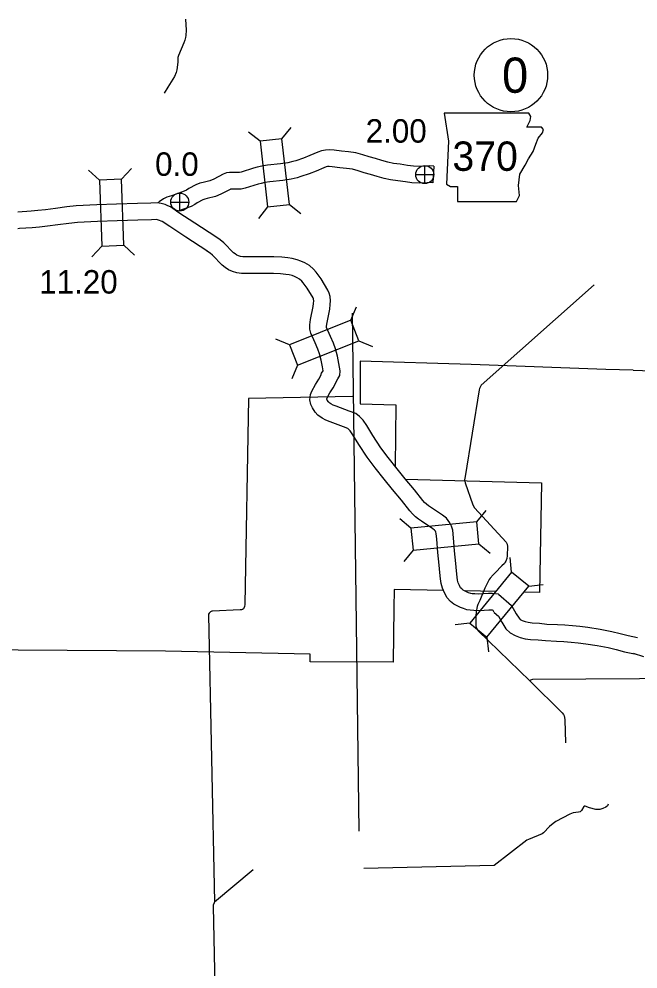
# Model space of a CAD drawing. Extents: x -939622 to -934245, y 1383184 to 1385301.
# Drawn here: x -936282.1 to -936248.7, y 1384082.8 to 1384134.1 of the extents above; entities that cross this region are included whole.
import ezdxf

# ---------------------------------------------------------------- set-up
doc = ezdxf.new("R2010")
doc.units = 0
for name, color, linetype in [('10', 7, 'Continuous'), ('20', 7, 'Continuous'), ('21', 7, 'Continuous'), ('25', 7, 'Continuous'), ('26', 7, 'Continuous'), ('27', 7, 'Continuous'), ('35', 7, 'Continuous'), ('8', 7, 'Continuous')]:
    doc.layers.add(name, color=color, linetype=linetype)

msp = doc.modelspace()

# ---------------------------------------------------------------- linework, layer by layer
at = {"layer": '10'}
for points in [[(-936259.691, 1384126.189), (-936259.9, 1384126.203), (-936260.112, 1384126.188), (-936260.441, 1384126.171), (-936260.797, 1384126.194), (-936261.113, 1384126.233), (-936261.51, 1384126.288), (-936261.874, 1384126.339), (-936262.17, 1384126.398), (-936262.501, 1384126.486), (-936262.845, 1384126.598), (-936263.188, 1384126.695), (-936263.52, 1384126.806), (-936263.899, 1384126.909), (-936264.302, 1384126.964), (-936264.673, 1384127), (-936265.074, 1384127.043), (-936265.325, 1384127.07), (-936265.545, 1384127.057), (-936265.753, 1384127.017), (-936265.962, 1384126.939), (-936266.383, 1384126.76), (-936266.733, 1384126.626), (-936267.14, 1384126.483), (-936267.306, 1384126.435), (-936267.569, 1384126.372), (-936267.967, 1384126.314), (-936268.676, 1384126.234), (-936268.981, 1384126.185), (-936269.221, 1384126.137), (-936269.428, 1384126.082), (-936270.099, 1384125.871), (-936270.185, 1384125.854), (-936270.339, 1384125.853), (-936270.727, 1384125.845), (-936270.888, 1384125.826), (-936271.073, 1384125.75), (-936271.57, 1384125.494), (-936271.78, 1384125.402), (-936272.142, 1384125.31), (-936272.323, 1384125.27), (-936272.539, 1384125.183), (-936272.917, 1384124.98), (-936273.049, 1384124.898), (-936273.165, 1384124.835), (-936273.456, 1384124.727), (-936273.856, 1384124.594), (-936274.097, 1384124.517), (-936274.277, 1384124.416), (-936274.518, 1384124.262), (-936274.577, 1384124.205)], [(-936259.748, 1384125.291), (-936259.898, 1384125.301), (-936260.057, 1384125.29), (-936260.446, 1384125.269), (-936260.881, 1384125.297), (-936261.229, 1384125.34), (-936261.634, 1384125.396), (-936262.025, 1384125.451), (-936262.375, 1384125.521), (-936262.756, 1384125.623), (-936263.107, 1384125.737), (-936263.454, 1384125.835), (-936263.781, 1384125.944), (-936264.078, 1384126.025), (-936264.405, 1384126.07), (-936264.764, 1384126.104), (-936265.172, 1384126.148), (-936265.346, 1384126.167), (-936265.431, 1384126.162), (-936265.51, 1384126.147), (-936265.629, 1384126.103), (-936266.045, 1384125.925), (-936266.424, 1384125.78), (-936266.866, 1384125.626), (-936267.076, 1384125.565), (-936267.399, 1384125.487), (-936267.851, 1384125.422), (-936268.553, 1384125.342), (-936268.823, 1384125.298), (-936269.019, 1384125.26), (-936269.177, 1384125.218), (-936269.875, 1384124.998), (-936270.094, 1384124.954), (-936270.328, 1384124.953), (-936270.66, 1384124.947), (-936270.695, 1384124.932), (-936271.184, 1384124.681), (-936271.487, 1384124.548), (-936271.933, 1384124.434), (-936272.057, 1384124.407), (-936272.157, 1384124.366), (-936272.466, 1384124.2), (-936272.596, 1384124.12), (-936272.792, 1384124.013), (-936273.158, 1384123.878), (-936273.572, 1384123.74)], [(-936259.691, 1384126.189), (-936259.748, 1384125.291)], [(-936271.46, 1384122.371), (-936272.589, 1384123.117), (-936273.452, 1384123.673), (-936273.91, 1384123.989), (-936274.054, 1384124.052), (-936274.204, 1384124.116), (-936274.42, 1384124.175), (-936274.625, 1384124.206), (-936274.968, 1384124.194), (-936275.697, 1384124.171), (-936276.815, 1384124.137), (-936277.877, 1384124.097), (-936278.997, 1384124.047), (-936279.497, 1384123.993), (-936280.117, 1384123.911), (-936280.654, 1384123.835), (-936281.061, 1384123.79), (-936281.438, 1384123.763), (-936282.149, 1384123.711)], [(-936271.955, 1384121.62), (-936273.081, 1384122.363), (-936273.951, 1384122.924), (-936274.35, 1384123.199), (-936274.41, 1384123.226), (-936274.5, 1384123.263), (-936274.607, 1384123.293), (-936274.677, 1384123.303), (-936274.939, 1384123.295), (-936275.669, 1384123.271), (-936276.784, 1384123.237), (-936277.84, 1384123.198), (-936278.928, 1384123.15), (-936279.39, 1384123.099), (-936279.996, 1384123.02), (-936280.542, 1384122.942), (-936280.978, 1384122.894), (-936281.373, 1384122.865), (-936282.062, 1384122.815), (-936282.141, 1384122.805)], [(-936256.198, 1384103.088), (-936256.545, 1384103.118), (-936256.735, 1384103.118), (-936257.017, 1384103.11), (-936257.259, 1384103.092), (-936257.488, 1384103.099), (-936257.631, 1384103.109), (-936257.697, 1384103.12), (-936257.819, 1384103.16), (-936257.897, 1384103.185), (-936257.995, 1384103.241), (-936258.102, 1384103.301), (-936258.186, 1384103.368), (-936258.247, 1384103.428), (-936258.316, 1384103.558), (-936258.378, 1384103.698), (-936258.413, 1384103.834), (-936258.434, 1384104), (-936258.468, 1384104.352), (-936258.511, 1384104.743), (-936258.578, 1384105.418), (-936258.634, 1384106.128), (-936258.673, 1384106.534), (-936258.741, 1384106.749), (-936258.828, 1384106.94), (-936259.006, 1384107.187), (-936259.227, 1384107.344), (-936259.866, 1384107.775), (-936259.988, 1384107.856), (-936260.093, 1384107.938), (-936260.19, 1384108.033), (-936260.286, 1384108.148), (-936260.744, 1384108.725), (-936261.234, 1384109.307), (-936261.672, 1384109.85), (-936262.158, 1384110.459), (-936262.559, 1384110.99), (-936262.985, 1384111.644), (-936263.308, 1384112.181), (-936263.514, 1384112.473), (-936263.708, 1384112.679), (-936263.907, 1384112.829), (-936264.264, 1384112.959), (-936264.958, 1384113.224), (-936265.129, 1384113.292), (-936265.256, 1384113.362), (-936265.359, 1384113.431), (-936265.384, 1384113.459), (-936265.452, 1384113.565), (-936265.469, 1384113.602), (-936265.474, 1384113.628), (-936265.474, 1384113.631), (-936265.464, 1384113.652), (-936265.307, 1384113.959), (-936265.133, 1384114.229), (-936264.983, 1384114.498), (-936264.948, 1384114.59), (-936264.873, 1384114.701), (-936264.767, 1384114.891), (-936264.745, 1384115.143), (-936264.815, 1384115.534), (-936264.898, 1384115.923), (-936265.009, 1384116.324), (-936265.117, 1384116.627), (-936265.265, 1384116.996), (-936265.481, 1384117.483), (-936265.489, 1384117.513), (-936265.489, 1384117.549), (-936265.458, 1384117.747), (-936265.313, 1384118.469), (-936265.281, 1384118.717), (-936265.278, 1384118.923), (-936265.287, 1384119.149), (-936265.339, 1384119.336), (-936265.416, 1384119.499), (-936265.778, 1384120.101), (-936266.038, 1384120.461), (-936266.189, 1384120.627), (-936266.412, 1384120.821), (-936266.662, 1384120.967), (-936266.87, 1384121.057), (-936267.062, 1384121.136), (-936267.34, 1384121.207), (-936267.568, 1384121.237), (-936267.901, 1384121.275), (-936268.333, 1384121.289), (-936269.106, 1384121.302), (-936269.816, 1384121.293), (-936270.01, 1384121.3), (-936270.136, 1384121.316), (-936270.241, 1384121.349), (-936270.335, 1384121.392), (-936270.422, 1384121.449), (-936270.499, 1384121.513), (-936271.035, 1384122.057), (-936271.235, 1384122.22), (-936271.456, 1384122.369)], [(-936256.436, 1384102.102), (-936256.488, 1384102.203), (-936256.519, 1384102.212), (-936256.583, 1384102.218), (-936256.722, 1384102.218), (-936256.972, 1384102.211), (-936257.239, 1384102.191), (-936257.531, 1384102.2), (-936257.735, 1384102.214), (-936257.914, 1384102.244), (-936258.098, 1384102.305), (-936258.26, 1384102.357), (-936258.437, 1384102.457), (-936258.606, 1384102.552), (-936258.786, 1384102.694), (-936258.978, 1384102.886), (-936259.125, 1384103.163), (-936259.231, 1384103.401), (-936259.3, 1384103.667), (-936259.328, 1384103.903), (-936259.363, 1384104.26), (-936259.406, 1384104.649), (-936259.475, 1384105.337), (-936259.531, 1384106.05), (-936259.56, 1384106.353), (-936259.583, 1384106.426), (-936259.61, 1384106.486), (-936259.649, 1384106.539), (-936259.74, 1384106.604), (-936260.367, 1384107.027), (-936260.514, 1384107.125), (-936260.685, 1384107.259), (-936260.852, 1384107.421), (-936260.985, 1384107.581), (-936261.44, 1384108.155), (-936261.929, 1384108.735), (-936262.374, 1384109.287), (-936262.868, 1384109.907), (-936263.296, 1384110.472), (-936263.748, 1384111.166), (-936264.063, 1384111.69), (-936264.212, 1384111.902), (-936264.312, 1384112.007), (-936264.342, 1384112.03), (-936264.577, 1384112.115), (-936265.286, 1384112.386), (-936265.515, 1384112.478), (-936265.725, 1384112.593), (-936265.951, 1384112.745), (-936266.1, 1384112.909), (-936266.249, 1384113.139), (-936266.329, 1384113.323), (-936266.384, 1384113.574), (-936266.355, 1384113.865), (-936266.276, 1384114.042), (-936266.088, 1384114.409), (-936265.905, 1384114.693), (-936265.8, 1384114.881), (-936265.752, 1384115.006), (-936265.659, 1384115.145), (-936265.698, 1384115.36), (-936265.772, 1384115.709), (-936265.867, 1384116.052), (-936265.959, 1384116.308), (-936266.094, 1384116.646), (-936266.33, 1384117.179), (-936266.389, 1384117.389), (-936266.39, 1384117.617), (-936266.344, 1384117.906), (-936266.202, 1384118.614), (-936266.181, 1384118.781), (-936266.179, 1384118.911), (-936266.183, 1384119.01), (-936266.186, 1384119.021), (-936266.211, 1384119.073), (-936266.529, 1384119.604), (-936266.738, 1384119.892), (-936266.821, 1384119.983), (-936266.94, 1384120.088), (-936267.068, 1384120.163), (-936267.22, 1384120.228), (-936267.345, 1384120.28), (-936267.51, 1384120.322), (-936267.677, 1384120.344), (-936267.966, 1384120.376), (-936268.355, 1384120.389), (-936269.108, 1384120.402), (-936269.827, 1384120.393), (-936270.083, 1384120.402), (-936270.328, 1384120.433), (-936270.564, 1384120.507), (-936270.77, 1384120.601), (-936270.958, 1384120.724), (-936271.11, 1384120.851), (-936271.642, 1384121.39), (-936271.772, 1384121.497), (-936271.959, 1384121.623)], [(-936256.198, 1384103.088), (-936255.498, 1384102.478), (-936255.243, 1384102.028), (-936255.094, 1384101.787), (-936255.024, 1384101.72), (-936254.927, 1384101.665), (-936254.768, 1384101.605), (-936254.6, 1384101.569), (-936254.379, 1384101.54), (-936253.99, 1384101.51), (-936253.594, 1384101.472), (-936253.019, 1384101.445), (-936252.624, 1384101.423), (-936252.208, 1384101.392), (-936251.809, 1384101.352), (-936251.371, 1384101.299), (-936250.718, 1384101.201), (-936250.091, 1384101.076), (-936249.637, 1384100.966), (-936249.195, 1384100.851), (-936248.69, 1384100.75)], [(-936256.436, 1384102.102), (-936256.205, 1384101.901), (-936256.017, 1384101.57), (-936255.799, 1384101.216), (-936255.565, 1384100.992), (-936255.311, 1384100.848), (-936255.024, 1384100.74), (-936254.754, 1384100.681), (-936254.471, 1384100.645), (-936254.068, 1384100.614), (-936253.659, 1384100.574), (-936253.065, 1384100.546), (-936252.682, 1384100.525), (-936252.287, 1384100.495), (-936251.907, 1384100.457), (-936251.492, 1384100.407), (-936250.873, 1384100.314), (-936250.286, 1384100.197), (-936249.856, 1384100.093), (-936249.396, 1384099.974), (-936248.866, 1384099.868)], [(-936248.361, 1384099.706), (-936248.913, 1384099.88)]]:
    msp.add_lwpolyline(points, dxfattribs=at)
at = {"layer": '20'}
for p, q in [((-936267.895, 1384127.663), (-936267.402, 1384128.283)), ((-936269.076, 1384127.529), (-936269.695, 1384128.021)), ((-936277.747, 1384125.435), (-936278.328, 1384125.973)), ((-936276.56, 1384125.479), (-936276.021, 1384126.06)), ((-936267.491, 1384124.122), (-936266.871, 1384123.629)), ((-936268.672, 1384123.988), (-936269.165, 1384123.368)), ((-936277.614, 1384121.873), (-936278.152, 1384121.293)), ((-936276.426, 1384121.918), (-936275.846, 1384121.379)), ((-936264.18, 1384117.87), (-936263.869, 1384118.598)), ((-936267.489, 1384116.544), (-936268.217, 1384116.856)), ((-936263.738, 1384116.767), (-936263.01, 1384116.456)), ((-936267.047, 1384115.442), (-936267.358, 1384114.714)), ((-936260.926, 1384106.64), (-936261.537, 1384107.144)), ((-936257.378, 1384106.982), (-936256.875, 1384107.593)), ((-936257.265, 1384105.799), (-936256.653, 1384105.295)), ((-936260.812, 1384105.458), (-936261.316, 1384104.847)), ((-936255.493, 1384104.274), (-936255.573, 1384105.062)), ((-936254.573, 1384103.523), (-936253.785, 1384103.603)), ((-936257.746, 1384101.512), (-936258.534, 1384101.432)), ((-936256.825, 1384100.761), (-936256.745, 1384099.973))]:
    msp.add_line(p, q, dxfattribs=at)
for points in [[(-936267.491, 1384124.122), (-936267.895, 1384127.663), (-936269.076, 1384127.529), (-936268.672, 1384123.988)], [(-936277.747, 1384125.435), (-936277.614, 1384121.873), (-936276.426, 1384121.918), (-936276.56, 1384125.479)], [(-936267.047, 1384115.442), (-936263.738, 1384116.767), (-936264.18, 1384117.87), (-936267.489, 1384116.544)], [(-936257.378, 1384106.982), (-936260.926, 1384106.64), (-936260.812, 1384105.458), (-936257.265, 1384105.799)], [(-936255.493, 1384104.274), (-936257.746, 1384101.512), (-936256.825, 1384100.761), (-936254.573, 1384103.523)]]:
    msp.add_lwpolyline(points, close=True, dxfattribs=at)
at = {"layer": '21'}
msp.add_lwpolyline([(-936259.13, 1384129.053), (-936258.902, 1384127.531), (-936259.003, 1384125.221), (-936258.8, 1384125.094), (-936258.42, 1384125.094), (-936258.42, 1384124.282), (-936255.222, 1384124.282), (-936255.07, 1384124.612), (-936255.121, 1384125.145), (-936255.044, 1384125.754), (-936254.765, 1384126.236), (-936254.588, 1384126.592), (-936254.334, 1384126.972), (-936254.182, 1384127.378), (-936254.055, 1384127.708), (-936253.826, 1384127.987), (-936253.776, 1384128.165), (-936253.877, 1384128.292), (-936254.664, 1384128.292), (-936254.486, 1384128.647), (-936254.461, 1384128.876), (-936254.566, 1384129.051)], close=True, dxfattribs=at)
at = {"layer": '26'}
for p, q in [((-936260.18, 1384125.244), (-936260.18, 1384126.219)), ((-936260.667, 1384125.731), (-936259.692, 1384125.731)), ((-936273.409, 1384123.764), (-936273.409, 1384124.738)), ((-936273.896, 1384124.251), (-936272.921, 1384124.251))]:
    msp.add_line(p, q, dxfattribs=at)
for centre in [(-936260.18, 1384125.731), (-936273.409, 1384124.251)]:
    msp.add_circle(centre, 0.487, dxfattribs=at)
at = {"layer": '27'}
msp.add_circle((-936255.528, 1384131.1), 1.98, dxfattribs=at)
at = {"layer": '35'}
for points in [[(-936273.1, 1384134.132), (-936273.069, 1384133.533), (-936273.087, 1384133.243), (-936273.103, 1384133.132), (-936273.142, 1384132.983), (-936273.189, 1384132.85), (-936273.476, 1384132.167), (-936273.509, 1384132.054), (-936273.514, 1384131.807), (-936273.567, 1384131.386), (-936273.593, 1384131.247), (-936273.683, 1384131.023), (-936274.055, 1384130.455), (-936274.252, 1384130.131)], [(-936251.041, 1384119.79), (-936257.132, 1384114.369), (-936257.223, 1384114.18), (-936257.248, 1384114.107), (-936258.007, 1384109.437), (-936258.03, 1384109.256), (-936258, 1384109.09), (-936257.593, 1384107.903), (-936257.495, 1384107.746), (-936255.795, 1384105.899), (-936255.729, 1384105.782), (-936255.713, 1384105.661), (-936255.73, 1384105.146), (-936255.751, 1384105.006), (-936255.799, 1384104.871), (-936255.834, 1384104.804), (-936255.885, 1384104.738), (-936256.028, 1384104.619), (-936256.377, 1384104.243), (-936256.498, 1384104.13), (-936256.651, 1384103.951), (-936256.701, 1384103.871)], [(-936264.101, 1384118.257), (-936263.747, 1384090.292)], [(-936269.7, 1384113.638), (-936269.9, 1384102.522)], [(-936264.088, 1384113.751), (-936269.7, 1384113.638)], [(-936256.701, 1384103.871), (-936256.938, 1384103.401), (-936257.206, 1384102.743), (-936257.32, 1384102.529), (-936257.36, 1384102.41), (-936257.405, 1384102.132), (-936257.417, 1384101.89), (-936257.418, 1384101.392), (-936257.402, 1384101.27), (-936257.291, 1384101.104), (-936254.511, 1384098.407), (-936252.769, 1384096.679), (-936252.687, 1384096.584), (-936252.649, 1384096.522), (-936252.633, 1384096.432), (-936252.624, 1384096.307), (-936252.593, 1384095.065)], [(-936269.9, 1384102.522), (-936269.911, 1384102.415), (-936269.947, 1384102.326), (-936269.976, 1384102.294), (-936270.023, 1384102.264), (-936270.077, 1384102.242), (-936270.138, 1384102.23), (-936271.643, 1384102.175), (-936271.673, 1384102.17), (-936271.742, 1384102.137), (-936271.824, 1384102.059), (-936271.855, 1384102.003), (-936271.864, 1384101.959), (-936271.528, 1384086.472)], [(-936245.711, 1384098.532), (-936254.369, 1384098.471), (-936254.477, 1384098.434), (-936254.511, 1384098.407)], [(-936250.284, 1384091.741), (-936250.326, 1384091.657), (-936250.405, 1384091.582), (-936250.562, 1384091.509), (-936250.723, 1384091.468), (-936250.949, 1384091.466), (-936251.283, 1384091.554), (-936251.52, 1384091.642), (-936251.572, 1384091.644), (-936251.603, 1384091.616), (-936251.724, 1384091.397), (-936251.799, 1384091.329), (-936251.883, 1384091.311), (-936252.026, 1384091.306), (-936252.166, 1384091.285), (-936252.358, 1384091.204), (-936252.736, 1384091.016), (-936253.111, 1384090.812), (-936253.254, 1384090.711), (-936253.44, 1384090.546), (-936253.771, 1384090.207), (-936253.843, 1384090.147), (-936254.584, 1384089.84), (-936254.664, 1384089.808), (-936256.431, 1384088.439), (-936263.472, 1384088.274)], [(-936271.528, 1384086.472), (-936269.443, 1384088.218)], [(-936271.528, 1384086.472), (-936271.555, 1384086.427), (-936271.604, 1384086.3), (-936271.608, 1384086.247), (-936271.306, 1384071.502)]]:
    msp.add_lwpolyline(points, dxfattribs=at)
at = {"layer": '8'}
for points in [[(-936248.934, 1384115.169), (-936242.488, 1384114.941), (-936242.501, 1384122.789), (-936234.404, 1384122.646), (-936226.394, 1384122.505), (-936218.549, 1384122.373)], [(-936248.934, 1384115.169), (-936250.416, 1384115.216), (-936257.684, 1384115.482), (-936263.677, 1384115.66), (-936263.669, 1384113.353), (-936261.737, 1384113.306), (-936261.777, 1384109.992)], [(-936261.215, 1384109.285), (-936253.872, 1384109.098), (-936253.987, 1384103.167), (-936254.793, 1384103.185)], [(-936259.172, 1384103.284), (-936261.832, 1384103.344), (-936261.847, 1384102.335)], [(-936256.345, 1384103.22), (-936258.008, 1384103.257)], [(-936261.847, 1384102.335), (-936261.895, 1384099.41), (-936266.365, 1384099.429), (-936266.371, 1384099.844), (-936274.17, 1384100.013), (-936282.139, 1384100.069), (-936290.066, 1384100.152), (-936298.009, 1384100.224), (-936305.242, 1384100.36)]]:
    msp.add_lwpolyline(points, dxfattribs=at)

# ---------------------------------------------------------------- texts
at = {"layer": '20'}
msp.add_text('11.20', height=1.2672, dxfattribs=at).set_placement((-936280.998, 1384119.31))
at = {"layer": '21'}
msp.add_text('370', height=1.584, dxfattribs=at).set_placement((-936258.691, 1384125.936))
at = {"layer": '25'}
for s, p in [('2.00', (-936263.373, 1384127.457)), ('0.0', (-936274.74, 1384125.666))]:
    msp.add_text(s, height=1.2672, dxfattribs=at).set_placement(p)
at = {"layer": '27'}
msp.add_text('0', height=1.901, dxfattribs=at).set_placement((-936256.012, 1384130.15))

doc.saveas('drawing.dxf')
